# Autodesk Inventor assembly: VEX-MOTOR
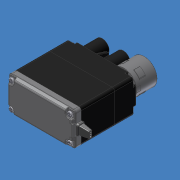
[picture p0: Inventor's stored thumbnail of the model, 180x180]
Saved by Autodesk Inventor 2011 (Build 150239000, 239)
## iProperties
Created: 2007-08
Part Number: VEX-MOTOR
Document SubType Name: Assembly
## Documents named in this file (10)
- C:\Data Folder\VEX 2011\Inventor Datasets\Unit 6\Components\VEX-MOTOR.iam
- C:\Data Folder\VEX 2011\Inventor Datasets\Unit 6\Components\Vex-Motor-Screw-Top-Simple.ipt
- C:\Data Folder\VEX 2011\Inventor Datasets\Unit 6\Components\Insert-Nut-632-Simple.ipt
- C:\Data Folder\VEX 2011\Inventor Datasets\Unit 6\Components\Vex-Motor-Top-Housing.ipt
- C:\Data Folder\VEX 2011\Inventor Datasets\Unit 6\Components\Vex-Motor-Screw-Bottom-Simple.ipt
- C:\Data Folder\VEX 2011\Inventor Datasets\Unit 6\Components\Vex-Motor-Output-Gear.ipt
- C:\Data Folder\VEX 2011\Inventor Datasets\Unit 6\Components\Vex-Motor-Bottom-Plate.ipt
- C:\Data Folder\VEX 2011\Inventor Datasets\Unit 6\Components\Vex-Motor-Bottom-Housing.ipt
- C:\Data Folder\VEX 2011\Inventor Datasets\Unit 6\Components\Vex-Wire-Support.ipt
- C:\Data Folder\VEX 2011\Inventor Datasets\Unit 6\Components\CLUTCH.iam
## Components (16 placed, 9 different names)
1. Vex-Motor-Screw-Top-Simple
2. Insert-Nut-632-Simple
3. Vex-Motor-Top-Housing
4. Vex-Motor-Screw-Bottom-Simple
5. Vex-Motor-Output-Gear — Insert:1
6. Insert-Nut-632-Simple
7. Vex-Motor-Screw-Top-Simple
8. Vex-Motor-Bottom-Plate
9. Vex-Motor-Screw-Top-Simple
10. Vex-Motor-Bottom-Housing
11. Vex-Motor-Screw-Bottom-Simple
12. Vex-Motor-Screw-Top-Simple
13. Vex-Wire-Support
14. Vex-Motor-Screw-Bottom-Simple
15. Vex-Motor-Screw-Bottom-Simple
16. CLUTCH:1 [sub-assembly] — Insert:1
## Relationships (1: Insert 1)
- Insert:1: Vex-Motor-Output-Gear ↔ CLUTCH:1
